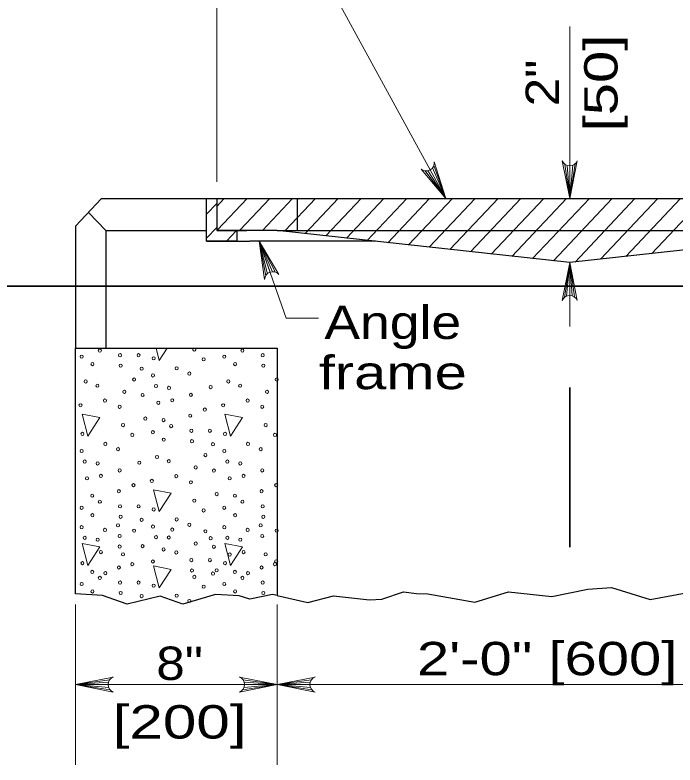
# Model space of a CAD drawing. Extents: x -410.5 to -376.5, y 1617.6 to 1661.6.
# Drawn here: x -405.643 to -402.554, y 1656.08 to 1659.586 of the extents above; entities that cross this region are included whole.
import ezdxf
from ezdxf.enums import TextEntityAlignment as Align

# ---------------------------------------------------------------- set-up
doc = ezdxf.new("R2010")
doc.units = 0
doc.header["$LTSCALE"] = 0.062
doc.layers.add('1', color=7, linetype='Continuous', lineweight=13)

msp = doc.modelspace()

# ---------------------------------------------------------------- linework, layer by layer
at = {"layer": '1'}
for p, q in [((-404.69908, 1658.80683), (-404.69908, 1659.92217)), ((-403.04708, 1659.53258), (-403.04708, 1658.72817)), ((-403.68317, 1658.88208), (-403.62667, 1658.72817)), ((-403.0695, 1658.88833), (-403.04708, 1658.72817)), ((-403.05842, 1658.88292), (-403.04708, 1658.72817)), ((-403.02233, 1658.89025), (-403.04708, 1658.72817)), ((-403.03275, 1658.88417), (-403.04708, 1658.72817)), ((-403.04708, 1658.88133), (-403.04708, 1658.72817)), ((-403.72358, 1658.85767), (-403.62667, 1658.72817)), ((-403.71125, 1658.85825), (-403.62667, 1658.72817)), ((-403.70058, 1658.86225), (-403.62667, 1658.72817)), ((-403.68933, 1658.87167), (-403.62667, 1658.72817)), ((-403.04708, 1658.72817), (-403.04708, 1658.87808)), ((-404.74633, 1658.65567), (-404.69917, 1658.70567)), ((-404.70058, 1658.68967), (-404.66417, 1658.72817)), ((-404.69908, 1658.72817), (-404.69908, 1658.57825)), ((-404.69583, 1658.5815), (-404.55733, 1658.72817)), ((-404.591, 1658.5795), (-404.4505, 1658.72817)), ((-404.48533, 1658.57825), (-404.34375, 1658.72817)), ((-404.3785, 1658.57825), (-404.23692, 1658.72817)), ((-404.3215, 1658.72375), (-404.31725, 1658.72817)), ((-404.28525, 1658.56392), (-404.13008, 1658.72817)), ((-404.1885, 1658.55333), (-404.02333, 1658.72817)), ((-404.09175, 1658.54275), (-403.91642, 1658.72825)), ((-403.99492, 1658.53208), (-403.80967, 1658.72817)), ((-403.89817, 1658.5215), (-403.70292, 1658.72817)), ((-403.80133, 1658.51092), (-403.59617, 1658.72817)), ((-403.7045, 1658.50025), (-403.48933, 1658.72825)), ((-403.60775, 1658.48967), (-403.38258, 1658.72817)), ((-403.511, 1658.47908), (-403.27575, 1658.72817)), ((-403.41417, 1658.4685), (-403.169, 1658.72817)), ((-403.31742, 1658.45783), (-403.06217, 1658.72817)), ((-403.22058, 1658.44725), (-402.95533, 1658.72817)), ((-403.12383, 1658.43675), (-402.84858, 1658.72817)), ((-403.02242, 1658.431), (-402.74175, 1658.72817)), ((-402.90333, 1658.44408), (-402.63492, 1658.72817)), ((-402.78417, 1658.457), (-402.52817, 1658.72817)), ((-402.66508, 1658.47008), (-402.42133, 1658.72817)), ((-404.74633, 1658.54267), (-404.69908, 1658.59258)), ((-404.65308, 1658.52825), (-404.60592, 1658.57825)), ((-404.4065, 1658.57725), (-404.4055, 1658.57825)), ((-404.358, 1658.57192), (-404.35208, 1658.57825)), ((-404.44933, 1658.384), (-404.5005, 1658.52833)), ((-404.462, 1658.3765), (-404.5005, 1658.52833)), ((-404.46975, 1658.36725), (-404.5005, 1658.52833)), ((-404.43808, 1658.38617), (-404.5005, 1658.52833)), ((-404.42583, 1658.38475), (-404.5005, 1658.52833)), ((-403.07192, 1658.26617), (-403.04708, 1658.42833)), ((-403.0615, 1658.27233), (-403.04708, 1658.42833)), ((-403.04708, 1658.27517), (-403.04708, 1658.42833)), ((-403.03575, 1658.2735), (-403.04708, 1658.42833)), ((-403.02467, 1658.26808), (-403.04708, 1658.42833)), ((-403.04708, 1658.42833), (-403.04708, 1658.13042)), ((-405.32842, 1657.71992), (-405.3015, 1657.61742)), ((-405.32842, 1657.11542), (-405.3015, 1657.01292)), ((-405.35992, 1656.07967), (-405.35992, 1656.82983)), ((-404.41592, 1656.07967), (-404.41592, 1656.82983)), ((-405.19967, 1656.47817), (-405.35992, 1656.45575)), ((-405.20508, 1656.46708), (-405.35992, 1656.45575)), ((-404.57617, 1656.47817), (-404.41592, 1656.45575)), ((-404.57075, 1656.46708), (-404.41592, 1656.45575)), ((-404.25567, 1656.47817), (-404.41592, 1656.45575)), ((-404.26108, 1656.46708), (-404.41592, 1656.45575)), ((-405.20675, 1656.45575), (-405.35992, 1656.45575)), ((-405.20392, 1656.44133), (-405.35992, 1656.45575)), ((-405.19775, 1656.43092), (-405.35992, 1656.45575)), ((-404.578, 1656.43092), (-404.41592, 1656.45575)), ((-404.57192, 1656.44133), (-404.41592, 1656.45575)), ((-404.56908, 1656.45575), (-404.41592, 1656.45575)), ((-404.41592, 1656.45575), (-402.47617, 1656.45575)), ((-404.26275, 1656.45575), (-404.41592, 1656.45575)), ((-404.25992, 1656.44133), (-404.41592, 1656.45575)), ((-404.25375, 1656.43092), (-404.41592, 1656.45575))]:
    msp.add_line(p, q, dxfattribs=at)
at = {"layer": '1', "lineweight": 25}
for p, q in [((-405.35992, 1658.59883), (-405.23783, 1658.72817)), ((-404.69908, 1658.72817), (-404.69908, 1658.57825)), ((-405.21833, 1658.57825), (-405.29883, 1658.6635)), ((-405.35992, 1658.59883), (-405.35992, 1658.0285)), ((-405.21833, 1658.57825), (-405.21833, 1658.0285)), ((-405.21833, 1658.57825), (-404.74833, 1658.57825)), ((-404.54433, 1658.57825), (-404.69908, 1658.57825)), ((-404.3215, 1658.57825), (-401.77275, 1658.57825)), ((-404.74633, 1658.52825), (-404.54433, 1658.52825)), ((-403.95592, 1658.52825), (-404.54433, 1658.52825))]:
    msp.add_line(p, q, dxfattribs=at)
at = {"layer": '1', "lineweight": 35}
for p, q in [((-405.89092, 1658.31867), (-400.23342, 1658.31867)), ((-403.04708, 1657.09817), (-403.04708, 1657.84467))]:
    msp.add_line(p, q, dxfattribs=at)
at = {"layer": '1'}
for points in [[(-403.62667, 1658.72817), (-404.14675, 1659.67892), (-405.03058, 1659.67892)], [(-403.68108, 1658.90025), (-403.62667, 1658.72817), (-403.74308, 1658.86608)], [(-403.01175, 1658.90517), (-403.04708, 1658.72817), (-403.0825, 1658.90517)], [(-404.47475, 1658.34967), (-404.5005, 1658.52833), (-404.408, 1658.37325)], [(-404.5005, 1658.52833), (-404.3735, 1658.16925), (-404.22342, 1658.16925)], [(-403.0825, 1658.25133), (-403.04708, 1658.42833), (-403.01175, 1658.25133)], [(-404.983, 1658.0285), (-404.96775, 1657.97083), (-404.93108, 1658.0285)], [(-405.3015, 1657.61742), (-405.24658, 1657.70392), (-405.32842, 1657.71992)], [(-405.3015, 1657.01292), (-405.24658, 1657.09942), (-405.32842, 1657.11542)], [(-405.18292, 1656.42033), (-405.35992, 1656.45575), (-405.18292, 1656.49108)], [(-404.59292, 1656.42033), (-404.41592, 1656.45575), (-404.59292, 1656.49108)], [(-404.23892, 1656.42033), (-404.41592, 1656.45575), (-404.23892, 1656.49108)], [(-405.35992, 1656.45575), (-404.62875, 1656.45575), (-404.41592, 1656.45575)]]:
    msp.add_lwpolyline(points, dxfattribs=at)
at = {"layer": '1', "lineweight": 25}
for points in [[(-405.23783, 1658.72817), (-404.7935, 1658.72817), (-404.69908, 1658.72817), (-404.3215, 1658.72817), (-401.77275, 1658.72817), (-401.39508, 1658.72817), (-401.30075, 1658.72817)], [(-404.69908, 1658.72817), (-404.69908, 1658.57825), (-404.5575, 1658.57825)], [(-404.41592, 1658.57825), (-404.3215, 1658.57825), (-404.3215, 1658.72817)], [(-401.53675, 1658.57825), (-401.67833, 1658.57825), (-403.04708, 1658.42833), (-404.41592, 1658.57825), (-404.5575, 1658.57825)], [(-404.41592, 1656.87183), (-404.43733, 1656.87667), (-404.54342, 1656.85467), (-404.59358, 1656.871), (-404.7045, 1656.87733), (-404.85808, 1656.83125), (-404.96408, 1656.86892), (-405.11767, 1656.83192), (-405.23408, 1656.87167), (-405.35992, 1656.87975), (-405.35992, 1658.0285)], [(-405.35992, 1658.0285), (-404.41592, 1658.0285), (-404.41592, 1656.87183)], [(-404.41592, 1656.87183), (-404.2725, 1656.83983), (-404.153, 1656.87083), (-403.98442, 1656.85217), (-403.92575, 1656.855), (-403.82517, 1656.88925), (-403.76458, 1656.882), (-403.7105, 1656.87983), (-403.49083, 1656.84083), (-403.33433, 1656.88892), (-403.13075, 1656.86817), (-402.962, 1656.90217), (-402.852, 1656.909), (-402.67125, 1656.85375), (-402.5025, 1656.88475), (-402.27992, 1656.84675), (-402.12158, 1656.88275), (-402.07225, 1656.89375), (-401.81283, 1656.85558), (-401.67833, 1656.88817)]]:
    msp.add_lwpolyline(points, dxfattribs=at)
msp.add_lwpolyline([(-404.74633, 1658.52825), (-404.74633, 1658.72817), (-404.69908, 1658.72817), (-404.69908, 1658.57825), (-404.60475, 1658.57825), (-404.60475, 1658.52825)], close=True, dxfattribs=at)
at = {"layer": '1'}
for points in [[(-404.661, 1657.71992), (-404.634, 1657.61742), (-404.579, 1657.70392)], [(-404.99475, 1657.3665), (-404.96775, 1657.26417), (-404.91275, 1657.35058)], [(-404.661, 1657.11542), (-404.634, 1657.01292), (-404.579, 1657.09942)], [(-404.99475, 1657.01017), (-404.96775, 1656.90775), (-404.91275, 1656.99417)]]:
    msp.add_lwpolyline(points, close=True, dxfattribs=at)
for centre, start, end in [((-403.71899, 1658.89566), 230.93913, 6.76525), ((-403.04715, 1658.91942), 202.08782, 337.91395), ((-404.4366, 1658.34802), 41.58092, 177.40705), ((-403.04707, 1658.23701), 22.08782, 157.91395), ((-405.16861, 1656.45576), 112.08782, 247.91395), ((-404.60719, 1656.45576), 292.08605, 67.91218), ((-404.22461, 1656.45576), 112.08782, 247.91395)]:
    msp.add_arc(centre, 0.0382, start, end, dxfattribs=at)
for centre, major_axis in [((-405.24608, 1658.01751), (0, -0.00756)), ((-404.57858, 1658.01751), (0, -0.00756)), ((-405.33141, 1657.98889), (0, 0.00756)), ((-405.15147, 1657.99554), (0, -0.00756)), ((-405.06491, 1657.99554), (0, 0.00756)), ((-404.99377, 1657.98123), (0, -0.00756)), ((-404.76031, 1657.97646), (0, 0.00756)), ((-404.66391, 1657.98889), (0, 0.00756)), ((-404.48396, 1657.99554), (0, -0.00756)), ((-405.28063, 1657.9542), (0, -0.00756)), ((-405.1488, 1657.9469), (0, -0.00756)), ((-405.0505, 1657.93259), (0, 0.00756)), ((-404.88652, 1657.93447), (0, -0.00756)), ((-404.61312, 1657.9542), (0, -0.00756)), ((-404.48129, 1657.9469), (0, -0.00756)), ((-404.99738, 1657.90108), (0, 0.00756)), ((-404.82706, 1657.90968), (0, -0.00756)), ((-405.31217, 1657.87311), (0, -0.00756)), ((-405.08572, 1657.882), (0, 0.00756)), ((-404.64466, 1657.87311), (0, -0.00756)), ((-404.41821, 1657.882), (0, 0.00756)), ((-405.25721, 1657.85308), (0, -0.00756)), ((-405.13105, 1657.82446), (0, 0.00756)), ((-404.98292, 1657.85149), (0, 0.00756)), ((-404.92257, 1657.84284), (0, -0.00756)), ((-404.7276, 1657.84643), (0, -0.00756)), ((-404.5897, 1657.85308), (0, -0.00756)), ((-404.46354, 1657.82446), (0, 0.00756)), ((-405.04605, 1657.8095), (0, 0.00756)), ((-404.81983, 1657.81039), (0, -0.00756)), ((-405.33653, 1657.76145), (0, -0.00756)), ((-405.22211, 1657.78342), (0, 0.00756)), ((-405.15358, 1657.75479), (0, 0.00756)), ((-404.97218, 1657.77323), (0, 0.00756)), ((-404.90727, 1657.78471), (0, -0.00756)), ((-404.66902, 1657.76145), (0, -0.00756)), ((-404.5546, 1657.78342), (0, 0.00756)), ((-404.48607, 1657.75479), (0, 0.00756)), ((-404.75469, 1657.74143), (0, -0.00756)), ((-405.03282, 1657.69949), (0, 0.00756)), ((-404.94776, 1657.69213), (0, 0.00756)), ((-404.82311, 1657.7128), (0, -0.00756)), ((-405.13734, 1657.66893), (0, 0.00756)), ((-404.91233, 1657.66416), (0, -0.00756)), ((-404.46983, 1657.66893), (0, 0.00756)), ((-405.32752, 1657.62788), (0, -0.00756)), ((-405.09406, 1657.62311), (0, 0.00756)), ((-404.99766, 1657.63554), (0, 0.00756)), ((-404.81771, 1657.64219), (0, -0.00756)), ((-404.73116, 1657.64219), (0, 0.00756)), ((-404.66001, 1657.62788), (0, -0.00756)), ((-404.42655, 1657.62311), (0, 0.00756)), ((-405.22027, 1657.58112), (0, -0.00756)), ((-404.94687, 1657.60085), (0, -0.00756)), ((-404.81504, 1657.59355), (0, -0.00756)), ((-404.71675, 1657.57924), (0, 0.00756)), ((-404.55277, 1657.58112), (0, -0.00756)), ((-405.33114, 1657.54773), (0, 0.00756)), ((-405.16081, 1657.55633), (0, -0.00756)), ((-404.66363, 1657.54773), (0, 0.00756)), ((-404.4933, 1657.55633), (0, -0.00756)), ((-404.97841, 1657.51976), (0, -0.00756)), ((-404.75196, 1657.52865), (0, 0.00756)), ((-405.31667, 1657.49814), (0, 0.00756)), ((-405.25632, 1657.48949), (0, -0.00756)), ((-405.06135, 1657.49308), (0, -0.00756)), ((-404.92346, 1657.49973), (0, -0.00756)), ((-404.7973, 1657.47111), (0, 0.00756)), ((-404.64917, 1657.49814), (0, 0.00756)), ((-404.58881, 1657.48949), (0, -0.00756)), ((-405.15358, 1657.45704), (0, -0.00756)), ((-404.7123, 1657.45615), (0, 0.00756)), ((-404.48607, 1657.45704), (0, -0.00756)), ((-405.30594, 1657.41988), (0, 0.00756)), ((-405.24102, 1657.43136), (0, -0.00756)), ((-405.00278, 1657.4081), (0, -0.00756)), ((-404.88836, 1657.43007), (0, 0.00756)), ((-404.81983, 1657.40144), (0, 0.00756)), ((-404.63843, 1657.41988), (0, 0.00756)), ((-404.57351, 1657.43136), (0, -0.00756)), ((-405.08844, 1657.38808), (0, -0.00756)), ((-404.42093, 1657.38808), (0, -0.00756)), ((-405.28152, 1657.33878), (0, 0.00756)), ((-405.15686, 1657.35945), (0, -0.00756)), ((-404.69906, 1657.34614), (0, 0.00756)), ((-404.61401, 1657.33878), (0, 0.00756)), ((-404.48935, 1657.35945), (0, -0.00756)), ((-405.24608, 1657.31081), (0, -0.00756)), ((-404.80358, 1657.31558), (0, 0.00756)), ((-404.57858, 1657.31081), (0, -0.00756)), ((-405.33141, 1657.28219), (0, 0.00756)), ((-405.15147, 1657.28884), (0, -0.00756)), ((-405.06491, 1657.28884), (0, 0.00756)), ((-404.99377, 1657.27453), (0, -0.00756)), ((-404.76031, 1657.26976), (0, 0.00756)), ((-404.66391, 1657.28219), (0, 0.00756)), ((-404.48396, 1657.28884), (0, -0.00756)), ((-405.28063, 1657.2475), (0, -0.00756)), ((-405.1488, 1657.2402), (0, -0.00756)), ((-405.0505, 1657.22589), (0, 0.00756)), ((-404.88652, 1657.22777), (0, -0.00756)), ((-404.61312, 1657.2475), (0, -0.00756)), ((-404.48129, 1657.2402), (0, -0.00756)), ((-405.33114, 1657.19141), (0, 0.00756)), ((-405.16081, 1657.20001), (0, -0.00756)), ((-404.99738, 1657.19438), (0, 0.00756)), ((-404.82706, 1657.20298), (0, -0.00756)), ((-404.66363, 1657.19141), (0, 0.00756)), ((-404.4933, 1657.20001), (0, -0.00756)), ((-405.22211, 1657.17891), (0, 0.00756)), ((-405.08572, 1657.1753), (0, 0.00756)), ((-404.90727, 1657.18021), (0, -0.00756)), ((-404.75196, 1657.17233), (0, 0.00756)), ((-404.5546, 1657.17891), (0, 0.00756)), ((-404.41821, 1657.1753), (0, 0.00756)), ((-405.31668, 1657.14182), (0, 0.00756)), ((-405.25632, 1657.13317), (0, -0.00756)), ((-405.15358, 1657.15029), (0, 0.00756)), ((-404.98292, 1657.14479), (0, 0.00756)), ((-404.92346, 1657.14341), (0, -0.00756)), ((-404.7276, 1657.13973), (0, -0.00756)), ((-404.64917, 1657.14182), (0, 0.00756)), ((-404.58881, 1657.13317), (0, -0.00756)), ((-404.48607, 1657.15029), (0, 0.00756)), ((-405.15358, 1657.10072), (0, -0.00756)), ((-405.04605, 1657.1028), (0, 0.00756)), ((-404.94776, 1657.08763), (0, 0.00756)), ((-404.7973, 1657.11479), (0, 0.00756)), ((-404.7123, 1657.09983), (0, 0.00756)), ((-405.24102, 1657.07504), (0, -0.00756)), ((-405.13734, 1657.06443), (0, 0.00756)), ((-404.88836, 1657.07374), (0, 0.00756)), ((-404.63843, 1657.06356), (0, 0.00756)), ((-404.57352, 1657.07504), (0, -0.00756)), ((-404.46983, 1657.06443), (0, 0.00756)), ((-405.32752, 1657.02338), (0, -0.00756)), ((-405.09406, 1657.01861), (0, 0.00756)), ((-404.99766, 1657.03103), (0, 0.00756)), ((-404.81771, 1657.03769), (0, -0.00756)), ((-404.73116, 1657.03769), (0, 0.00756)), ((-404.66001, 1657.02338), (0, -0.00756)), ((-404.42655, 1657.01861), (0, 0.00756)), ((-404.42093, 1657.03175), (0, -0.00756)), ((-405.28152, 1656.98246), (0, 0.00756)), ((-405.15686, 1657.00313), (0, -0.00756)), ((-404.81504, 1656.98904), (0, -0.00756)), ((-404.69906, 1656.98982), (0, 0.00756)), ((-404.61401, 1656.98246), (0, 0.00756)), ((-404.48935, 1657.00313), (0, -0.00756)), ((-405.24609, 1656.95449), (0, -0.00756)), ((-405.22028, 1656.97662), (0, -0.00756)), ((-404.80358, 1656.95926), (0, 0.00756)), ((-404.71675, 1656.97473), (0, 0.00756)), ((-404.57858, 1656.95449), (0, -0.00756)), ((-404.55277, 1656.97662), (0, -0.00756)), ((-405.33142, 1656.92587), (0, 0.00756)), ((-405.15147, 1656.93252), (0, -0.00756)), ((-405.06491, 1656.93252), (0, 0.00756)), ((-404.99377, 1656.91821), (0, -0.00756)), ((-404.76031, 1656.91344), (0, 0.00756)), ((-404.66391, 1656.92587), (0, 0.00756)), ((-404.48396, 1656.93252), (0, -0.00756)), ((-405.28063, 1656.89118), (0, -0.00756)), ((-405.1488, 1656.88388), (0, -0.00756)), ((-404.61312, 1656.89118), (0, -0.00756)), ((-404.48129, 1656.88388), (0, -0.00756)), ((-405.05051, 1656.86957), (0, 0.00756)), ((-404.88652, 1656.87145), (0, -0.00756)), ((-404.82706, 1656.84666), (0, -0.00756))]:
    msp.add_ellipse(centre, major_axis=major_axis, ratio=0.944543, dxfattribs=at)
msp.add_ellipse((-404.80366, 1658.0222), major_axis=(0, 0.00756), ratio=0.944543, start_param=0.5891114, end_param=5.6903414, dxfattribs=at)

# ---------------------------------------------------------------- texts
for s, width, p in [('[50]', 1.3, (-402.8235, 1659.26829)), ('2"', 1.15, (-403.0975, 1659.26829))]:
    msp.add_text(s, height=0.156, rotation=90, dxfattribs=dict(at, width=width)).set_placement(p, align=Align.CENTER)
for s, width, p in [('Angle', 1.2, (-403.87517, 1658.0715)), ('frame', 1.3, (-403.87517, 1657.83683)), ('8"', 1.15, (-404.87275, 1656.47733)), ('[200]', 1.35, (-404.87275, 1656.20333))]:
    msp.add_text(s, height=0.156, dxfattribs=dict(at, width=width)).set_placement(p, align=Align.CENTER)
at = {"layer": '1', "width": 1.3}
msp.add_text('2\'-0" [600]', height=0.156, dxfattribs=at).set_placement((-403.76217, 1656.49933))

doc.saveas('drawing.dxf')
